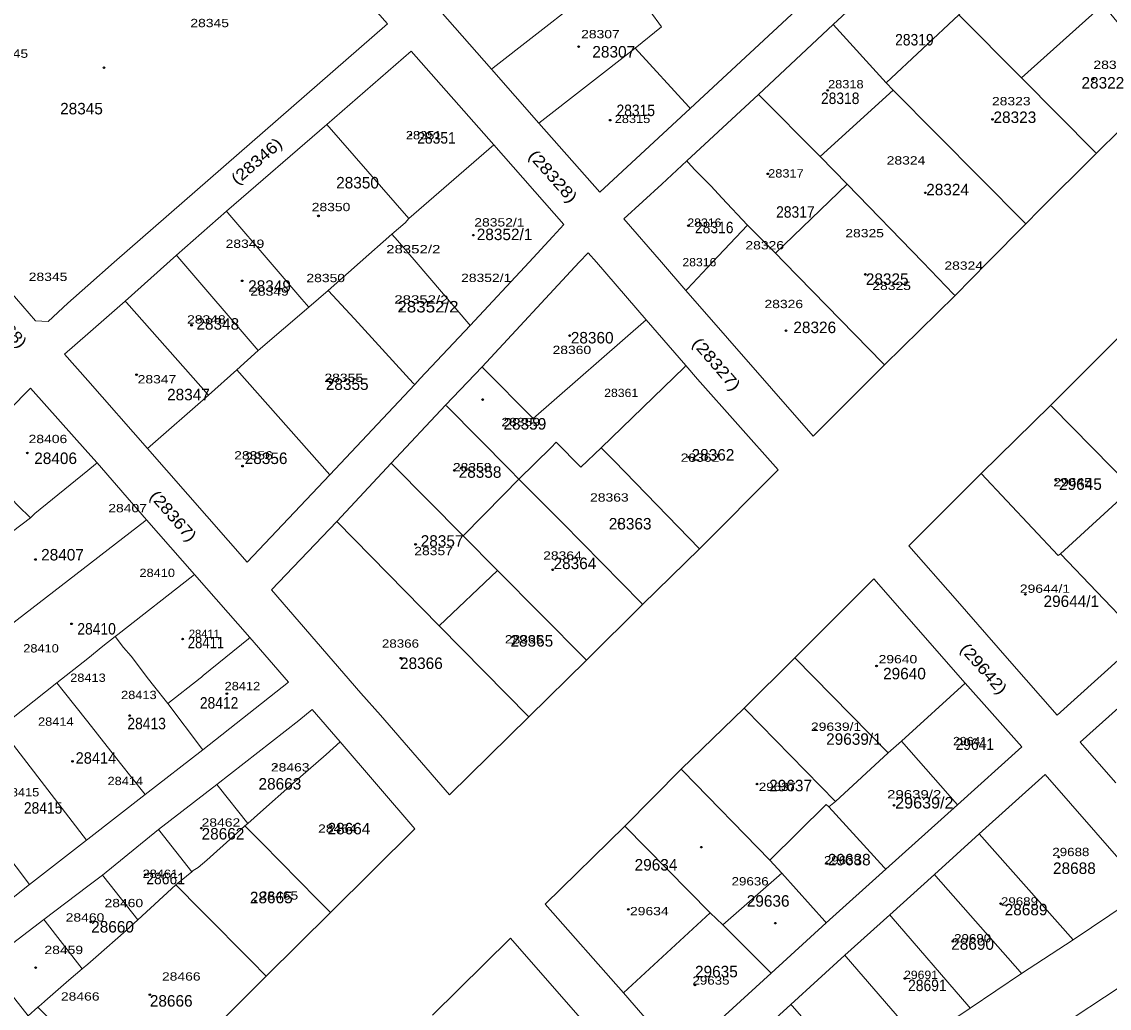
# Model space of a CAD drawing. Extents: x 650553 to 652508, y 239277 to 241647.
# Drawn here: x 651729.3 to 652069.7, y 240766.6 to 241075.2 of the extents above; entities that cross this region are included whole.
import ezdxf

# ---------------------------------------------------------------- set-up
doc = ezdxf.new("R2010")
doc.units = 0
doc.header["$PDMODE"] = 32
doc.header["$PDSIZE"] = 0.5
for name, color, linetype in [('19', 7, 'Continuous'), ('20', 7, 'Continuous'), ('6', 7, 'Continuous')]:
    doc.layers.add(name, color=color, linetype=linetype)
doc.layers.add('3', color=7, linetype='Continuous', lineweight=13)
doc.layers.add('5', color=7, linetype='Continuous', lineweight=13)

msp = doc.modelspace()

# ---------------------------------------------------------------- linework, layer by layer
at = {"layer": '3'}
for p, q in [((651924.77, 240982), (651909.19, 240999.99)), ((651750, 240963.02), (651768.69, 240941.77)), ((651825.74, 240933.5), (651852.36, 240961.71)), ((652021.51, 240894.81), (652038.48, 240875.31)), ((651835.45, 240865.24), (651841.63, 240858.29)), ((651731.81, 240805.34), (651749.66, 240819.26)), ((651825.99, 240796.59), (651805.82, 240776.71))]:
    msp.add_line(p, q, dxfattribs=at)
for points in [[(652017.226, 241141.527), (652026.85, 241129.84), (651999.05, 241104.25), (651938.56, 241048.11), (651910.25, 241021.92), (651891.181, 241043.471), (651876.36, 241060.41), (651857.991, 241081.221), (651845.55, 241095.34), (651829.37, 241113.9)], [(651737.63, 240981.45), (651733.68, 240981.72), (651717.72, 241000), (651672.26, 241052.06), (651672.58, 241053.6), (651750, 241112.87), (651779.79, 241135.68), (651785.77, 241140.28)], [(651785.77, 241140.28), (651790.81, 241134.55), (651843.78, 241074.53), (651758.28, 241000), (651750, 240992.68), (651743.815, 240987.217), (651737.63, 240981.45)], [(651983.33, 241074.4), (652010.17, 241099.35), (652014.44, 241103.34), (652034.04, 241121.44)], [(652067.78, 241080.53), (652087.98, 241056.04), (652065.72, 241034.07)], [(651959.92, 241052.49), (651959.88, 241052.46), (651983.33, 241074.4)], [(651877.11, 241036.75), (651851.25, 241066.02), (651824.88, 241043.11)], [(651937.23, 240991.2), (651929.59, 240999.98), (651917.75, 241013.6), (651929.68, 241024.44), (651937.53, 241031.7), (651959.92, 241052.49)], [(651750, 240977.6), (651761.72, 240987.86), (651777.78, 241002.17), (651793.43, 241015.96), (651824.88, 241043.11)], [(651888.11, 240999.99), (651895.59, 241008.03), (651898.96, 241011.76), (651877.11, 241036.75)], [(652065.72, 241034.07), (652047.38, 241015.92), (652044.07, 241012.53), (652043.58, 241011.99)], [(652043.58, 241011.99), (652031.74, 240999.98), (652021.48, 240989.55), (651999.33, 240967.9), (651976.99, 240945.59), (651937.23, 240991.2)], [(651909.19, 240999.99), (651906.59, 241002.99), (651903.81, 240999.99)], [(651903.81, 240999.99), (651873.4, 240967.25), (651862.01, 240955.34), (651844.95, 240937.15), (651827.99, 240918.9)], [(651852.36, 240961.71), (651854.09, 240963.61), (651869.71, 240980.19), (651888.11, 240999.99)], [(652029.57, 240933.88), (652051.36, 240955.22), (652072.28, 240976.15), (652095.19, 240998.75), (652096.4, 240999.97)], [(651940.85, 240963.44), (651937.22, 240967.66), (651924.77, 240982)], [(651750, 240977.6), (651742.76, 240971.25), (651750, 240963.02)], [(651941.49, 240910.36), (651966.07, 240935.03), (651940.85, 240963.44)], [(651712.06, 240940.35), (651732.06, 240960.6), (651750, 240940.5)], [(651768.69, 240941.77), (651799.93, 240906.14), (651825.74, 240933.5)], [(651812.82, 240868.68), (651800.77, 240882.58), (651783.43, 240902.3), (651768.4, 240919.43), (651752.95, 240937.2), (651750, 240940.5)], [(652021.51, 240894.81), (652006.93, 240911.31), (652029.57, 240933.88)], [(651827.99, 240918.9), (651807.54, 240897.54), (651835.45, 240865.24)], [(651888.09, 240857.77), (651906.06, 240875.49), (651923.67, 240892.98), (651941.49, 240910.36)], [(651971.34, 240876.28), (651996.04, 240900.92), (652024.65, 240868.28)], [(652038.48, 240875.31), (652053.43, 240858.34), (652079.85, 240882.2)], [(651918.05, 240823.64), (651935.73, 240841.37), (651955.41, 240860.55), (651971.34, 240876.28)], [(652071.8, 240837.17), (652060.65, 240849.83), (652086.59, 240873.17)], [(651785.973, 240847.456), (651786.03, 240847.5), (651812.82, 240868.68)], [(652024.65, 240868.28), (652042.35, 240848.37), (652022.25, 240830.22)], [(651828.96, 240849.94), (651820.2, 240860.04), (651816.02, 240856.68)], [(651736.3, 240794.4), (651750, 240804.78), (651754.61, 240808.27), (651772.19, 240822.5), (651790.39, 240836.59), (651816.02, 240856.68)], [(651841.63, 240858.29), (651863.19, 240833.39), (651888.09, 240857.77)], [(651825.99, 240796.59), (651852.4, 240822.8), (651828.96, 240849.94)], [(651749.66, 240819.26), (651750, 240819.52), (651767.96, 240833.48), (651785.973, 240847.456)], [(652029.04, 240821.24), (652049.7, 240839.74), (652081.4, 240803.43), (652058.39, 240788.05)], [(652022.25, 240830.22), (651999.75, 240810.11), (651981.15, 240793.34), (651963.94, 240777.64)], [(651917.67, 240771.45), (651893.13, 240799.24), (651918.05, 240823.64)], [(651950.46, 240750), (651970.1, 240767.82), (651986.91, 240783.26), (652001.01, 240795.81), (652014.98, 240808.48), (652029.04, 240821.24)], [(651731.81, 240805.34), (651713.76, 240791.05), (651698.26, 240811.09)], [(652130.48, 240811.26), (652125, 240807.76), (652110.91, 240798.75), (652092.01, 240785.99), (652073.09, 240773.31), (652053.84, 240760.57)], [(651666.816, 240692.253), (651642.596, 240721.898), (651682.54, 240752.71), (651700.34, 240766.81), (651718.3, 240780.69), (651736.3, 240794.4)], [(651857.87, 240764.46), (651882.29, 240788.58), (651910.691, 240756.161)], [(652058.39, 240788.05), (652042.27, 240777.48), (652026.22, 240766.64), (652010.4, 240756.05)], [(651963.94, 240777.64), (651935.1, 240751.32), (651917.67, 240771.45)], [(651805.82, 240776.71), (651779.01, 240750), (651765.5, 240736.54), (651749.871, 240721.656)]]:
    msp.add_lwpolyline(points, dxfattribs=at)
at = {"layer": '5'}
for p, q in [((651921.28, 241066.98), (651891.181, 241043.471)), ((651979.18, 241033.11), (652002.09, 241053.88)), ((651987.64, 241024.46), (652011.37, 240999.98)), ((651956.51, 241011.57), (651945.54, 240999.98)), ((651968.01, 240999.98), (651965.22, 241002.84)), ((651825.27, 240991.12), (651835.27, 240999.99)), ((651889.37, 240951.15), (651924.77, 240982)), ((651796.62, 240966.3), (651803.34, 240972.4)), ((651894.99, 240942.09), (651896.58, 240943.72)), ((651914.77, 240937.9), (651910.68, 240941.95)), ((651914.77, 240937.9), (651941.49, 240910.36)), ((651878.24, 240903.55), (651867.53, 240914.39)), ((652054.4, 240908.79), (652079.85, 240882.2)), ((651859.97, 240886.3), (651888.09, 240857.77)), ((651758.59, 240882.9), (651759.45, 240883.57)), ((652004.7, 240850.14), (652024.65, 240868.28)), ((651984, 240831.33), (652000.54, 240846.49)), ((652029.04, 240821.24), (652058.39, 240788.05)), ((651948.76, 240792.69), (651967.25, 240808.86)), ((651765.65, 240794.27), (651777.555, 240805.204)), ((651785.53, 240797.18), (651777.555, 240805.204)), ((651748.28, 240778.98), (651744.1, 240775.4)), ((651750, 240780.46), (651748.28, 240778.98)), ((651734.39, 240766.92), (651735.38, 240767.79))]:
    msp.add_line(p, q, dxfattribs=at)
for points in [[(651916.06, 241091.42), (651876.86, 241060.801), (651876.36, 241060.41)], [(652030.93, 241084.96), (652022.59, 241077.39), (651999.92, 241056.14)], [(652067.78, 241080.53), (652067.28, 241080.083), (652042.2, 241057.65), (652022.59, 241077.39)], [(651925.9, 241078.62), (651929.61, 241073.6), (651921.28, 241066.98)], [(651983.33, 241074.4), (651999.92, 241056.14), (652002.09, 241053.88)], [(651921.28, 241066.98), (651938.102, 241048.61), (651938.56, 241048.11)], [(652042.2, 241057.65), (652065.221, 241034.57), (652065.72, 241034.07)], [(652002.09, 241053.88), (652043.085, 241012.49), (652043.58, 241011.99)], [(651937.53, 241031.7), (651937.961, 241031.2), (651939.96, 241028.88), (651945.1, 241023.75), (651948.44, 241020.15), (651956.51, 241011.57), (651965.22, 241002.84), (651987.64, 241024.46), (651979.18, 241033.11), (651959.92, 241052.49)], [(651824.88, 241043.11), (651850.49, 241013.64), (651877.11, 241036.75)], [(651793.43, 241015.96), (651793.858, 241015.46), (651807.08, 241000)], [(651850.49, 241013.64), (651849.33, 241012.33), (651845.14, 241008.75), (651835.27, 240999.99)], [(651852.75, 240999.99), (651846.94, 241006.77), (651845.14, 241008.75)], [(651803.34, 240972.4), (651778.209, 241001.67), (651777.78, 241002.17)], [(651807.08, 241000), (651816.96, 240988.45), (651819.25, 240985.9), (651803.34, 240972.4)], [(651852.75, 240999.99), (651869.282, 240980.69), (651869.71, 240980.19)], [(651945.54, 240999.98), (651937.703, 240991.7), (651937.23, 240991.2)], [(651968.01, 240999.98), (651998.842, 240968.4), (651999.33, 240967.9)], [(652011.37, 240999.98), (652020.995, 240990.05), (652021.48, 240989.55)], [(651819.25, 240985.9), (651825.27, 240991.12), (651833.47, 240982.33)], [(651787.8, 240958.43), (651762.163, 240987.36), (651761.72, 240987.86)], [(651833.47, 240982.33), (651851.902, 240962.21), (651852.36, 240961.71)], [(651768.69, 240941.77), (651787.8, 240958.43), (651796.62, 240966.3), (651825.74, 240933.5)], [(651873.4, 240967.25), (651873.896, 240966.75), (651889.37, 240951.15)], [(651937.22, 240967.66), (651936.72, 240967.176), (651910.68, 240941.95)], [(651862.01, 240955.34), (651862.506, 240954.84), (651882.11, 240935.08), (651884.94, 240932.09), (651898.61, 240918.47)], [(652051.36, 240955.22), (652051.853, 240954.72), (652076.91, 240929.32)], [(652054.4, 240908.79), (652076.91, 240929.32), (652098.09, 240948.54)], [(651867.53, 240914.39), (651880.14, 240927.2), (651884.94, 240932.09), (651894.99, 240942.09)], [(651910.68, 240941.95), (651904.32, 240935.86), (651896.58, 240943.72)], [(651750, 240934.8), (651733.48, 240921.37), (651732.05, 240920.07), (651728.26, 240923.78), (651722.22, 240930.07), (651712.06, 240940.35)], [(651752.95, 240937.2), (651752.45, 240936.793), (651750, 240934.8)], [(651867.53, 240914.39), (651845.446, 240936.65), (651844.95, 240937.15)], [(652029.57, 240933.88), (652053.74, 240908.25), (652054.4, 240908.79)], [(651713.094, 240876.806), (651767.9, 240919.045), (651768.4, 240919.43)], [(651732.05, 240920.07), (651723.48, 240913.44), (651715.51, 240907.39)], [(651827.99, 240918.9), (651859.97, 240886.3), (651878.24, 240903.55)], [(651898.61, 240918.47), (651923.178, 240893.48), (651923.67, 240892.98)], [(651878.24, 240903.55), (651905.564, 240875.99), (651906.06, 240875.49)], [(651759.45, 240883.57), (651782.93, 240901.909), (651783.43, 240902.3)], [(651785.57, 240870.227), (651785.16, 240869.906), (651775.02, 240861.97), (651770.62, 240867.62), (651769.03, 240869.62), (651763.58, 240876.74), (651761.23, 240879.53), (651758.59, 240882.9), (651754.75, 240879.85), (651750, 240876.09)], [(651800.77, 240882.58), (651800.27, 240882.174), (651786.16, 240870.706), (651785.57, 240870.227)], [(651708.23, 240872.56), (651708.622, 240872.06), (651722.51, 240854.34), (651740.3, 240868.43), (651750, 240876.09)], [(651971.34, 240876.28), (652000.54, 240846.49), (652004.7, 240850.14), (652022.25, 240830.22)], [(651740.3, 240868.43), (651742.32, 240865.93), (651750, 240856.19)], [(651785.973, 240847.456), (651785.593, 240847.96), (651775.02, 240861.97)], [(651955.41, 240860.55), (651955.899, 240860.05), (651984, 240831.33), (651981.92, 240829.6)], [(651767.96, 240833.48), (651767.563, 240833.98), (651760.26, 240843.17), (651750, 240856.19)], [(651722.51, 240854.34), (651723.48, 240853.25), (651724.39, 240852.09), (651749.66, 240819.26)], [(651828.96, 240849.94), (651824.63, 240846.06), (651814.23, 240836.89), (651804.06, 240827.93)], [(651704.72, 240840.47), (651707.99, 240836.04), (651712.92, 240829.92), (651716.78, 240824.93), (651719.91, 240820.96), (651723.46, 240816.36), (651731.81, 240805.34)], [(651935.73, 240841.37), (651936.219, 240840.87), (651963.46, 240813), (651967.25, 240808.86)], [(651790.39, 240836.59), (651790.786, 240836.09), (651800.06, 240824.38)], [(651963.46, 240813), (651981.12, 240830.41), (651981.92, 240829.6)], [(651981.92, 240829.6), (651999.293, 240810.61), (651999.75, 240810.11)], [(651795.51, 240820.38), (651799.16, 240823.7), (651800.06, 240824.38), (651804.06, 240827.93)], [(651772.19, 240822.5), (651772.583, 240822), (651782.529, 240809.355), (651777.555, 240805.204)], [(651825.99, 240796.59), (651821.82, 240800.72), (651804.59, 240818.24), (651799.16, 240823.7)], [(651918.05, 240823.64), (651944.81, 240796.43), (651917.67, 240771.45)], [(651782.529, 240809.355), (651783.029, 240809.686), (651784.56, 240810.7), (651787.32, 240812.95), (651795.51, 240820.38)], [(651754.61, 240808.27), (651755.004, 240807.77), (651765.65, 240794.27)], [(651967.25, 240808.86), (651980.702, 240793.84), (651981.15, 240793.34)], [(652014.98, 240808.48), (652015.42, 240807.98), (652041.83, 240777.98), (652042.27, 240777.48)], [(651736.3, 240794.4), (651736.688, 240793.9), (651748.28, 240778.98)], [(651805.82, 240776.71), (651805.33, 240777.21), (651801.69, 240780.92), (651785.53, 240797.18)], [(651944.81, 240796.43), (651948.76, 240792.69), (651963.94, 240777.64)], [(652001.01, 240795.81), (652001.442, 240795.31), (652025.788, 240767.14), (652026.22, 240766.64)], [(651765.65, 240794.27), (651761.99, 240790.97), (651752.52, 240782.62), (651750, 240780.46)], [(651986.91, 240783.26), (651987.342, 240782.76), (652009.968, 240756.55), (652010.4, 240756.05)], [(651718.3, 240780.69), (651718.697, 240780.19), (651731.34, 240764.27), (651734.39, 240766.92), (651736.58, 240764.83), (651750, 240751.45)], [(651744.1, 240775.4), (651736.61, 240768.88), (651735.38, 240767.79)], [(651970.1, 240767.82), (651970.539, 240767.32), (651985.73, 240750)]]:
    msp.add_lwpolyline(points, dxfattribs=at)
at = {"layer": '6'}
for p in [(651903.616, 241067.445), (651755.087, 241060.865), (652064.745, 241057.3), (651981.608, 241053.755), (651913.519, 241044.45), (652033.16, 241044.69), (651851.06, 241039.83), (651962.841, 241027.665), (652012.124, 241021.715), (651822.207, 241014.505), (651938.008, 241011.45), (651870.691, 241008.47), (651993.387, 240996.18), (651798.349, 240994.18), (651848.079, 240985.23), (651782.488, 240980.3), (651968.567, 240978.58), (651900.817, 240977.07), (651765.281, 240964.815), (651825.986, 240962.31), (651873.582, 240957.045), (651731.111, 240940.335), (651938.093, 240939.01), (651798.441, 240936.22), (651864.765, 240934.865), (652053.06, 240931.735), (651916.233, 240918.35), (651852.596, 240911.725), (651733.64, 240907.003), (651895.522, 240903.79), (652043.449, 240896.11), (651744.933, 240886.885), (651779.706, 240882.135), (651883.231, 240880.66), (651848.003, 240876.145), (651996.879, 240873.705), (651793.551, 240865.018), (651763.148, 240858.19), (651977.69, 240853.805), (652023.526, 240849.25), (651745.232, 240843.845), (651808.912, 240842.21), (651959.447, 240836.775), (652002.347, 240830.125), (651785.58, 240822.972), (651825.796, 240823.265), (651942.036, 240817.03), (651981.313, 240811.875), (652053.899, 240813.895), (651768.059, 240808.385), (651802.432, 240800.205), (651919.17, 240797.545), (652035.699, 240799.36), (651750.918, 240793.625), (651965.226, 240793.25), (652020.768, 240787.56), (651733.69, 240779.335), (651940.06, 240773.875), (652005.715, 240775.93), (651769.429, 240770.872)]:
    msp.add_point(p, dxfattribs=at)

# ---------------------------------------------------------------- texts
at = {"layer": '19'}
for s, width, p in [('28319', 0.9, (652002.695, 241067.806)), ('28318', 0.9, (651979.476, 241049.486)), ('28315', 0.9, (651915.49, 241045.716)), ('28351', 0.9, (651853.125, 241037.093)), ('28317', 0.9, (651965.438, 241013.923)), ('28316', 0.9, (651940.059, 241009.074)), ('28352/2', 1.1, (651846.915, 240984.288)), ('28410', 0.9, (651746.751, 240883.528)), ('28411', 0.85, (651781.309, 240879.217)), ('28412', 0.9, (651785.088, 240860.358)), ('28413', 0.9, (651762.41, 240853.892)), ('29641', 0.9, (652021.595, 240847.427)), ('28414', 0.95, (651746.211, 240843.116)), ('29639/2', 1.05, (652002.695, 240829.107)), ('28415', 0.9, (651730.012, 240827.49)), ('28661', 0.9, (651768.351, 240805.399)), ('28691', 0.9, (652006.745, 240771.994))]:
    msp.add_text(s, height=3.6, dxfattribs=dict(at, width=width)).set_placement(p)
for s, p in [('28307', (651907.931, 241064.037)), ('28322', (652061.011, 241054.336)), ('28345', (651741.351, 241046.253)), ('28323', (652033.473, 241043.559)), ('28350', (651827.746, 241023.084)), ('28324', (652012.413, 241020.929)), ('28352/1', (651871.754, 241006.919)), ('28325', (651993.515, 240992.91)), ('28349', (651800.209, 240990.754)), ('28348', (651784.009, 240978.9)), ('28360', (651901.182, 240974.59)), ('28326', (651970.838, 240977.823)), ('28355', (651824.507, 240960.041)), ('28347', (651774.83, 240956.808)), ('28359', (651880.124, 240947.648)), ('28362', (651938.98, 240937.949)), ('28406', (651733.252, 240936.872)), ('28356', (651799.13, 240936.872)), ('28358', (651866.084, 240932.561)), ('29645', (652053.993, 240928.789)), ('28363', (651913.062, 240916.396)), ('28357', (651854.206, 240911.008)), ('28407', (651735.412, 240906.698)), ('28364', (651895.782, 240904.004)), ('29644/1', (652049.132, 240892.149)), ('28365', (651882.284, 240879.756)), ('28366', (651847.726, 240872.752)), ('29640', (651998.915, 240869.519)), ('29639/1', (651981.096, 240849.043)), ('28663', (651803.449, 240835.035)), ('29637', (651963.278, 240834.495)), ('28662', (651785.63, 240819.409)), ('28664', (651825.047, 240821.025)), ('29638', (651981.636, 240811.326)), ('29634', (651921.16, 240809.709)), ('28688', (652052.102, 240808.634)), ('28665', (651800.749, 240799.472)), ('29636', (651956.258, 240798.394)), ('28689', (652036.983, 240795.702)), ('28660', (651751.072, 240790.312)), ('28690', (652020.244, 240784.926)), ('29635', (651940.059, 240776.302)), ('28666', (651769.431, 240767.143))]:
    msp.add_text(s, height=3.6, dxfattribs=at).set_placement(p)
for s, rotation, width, p in [('(28346)', 40.803, 1.15, (651796.796, 241024.054)), ('(28328)', 311.43, 1.2, (651887.688, 241033.163)), ('(28368)', 311.011, 1.15, (651716.05, 240987.226)), ('(28327)', 310.702, 1.2, (651938.931, 240974.507)), ('(28367)', 311.005, 1.15, (651769.164, 240926.668)), ('(29642)', 311.236, 1.15, (652022.769, 240878.85))]:
    msp.add_text(s, height=3.6, rotation=rotation, dxfattribs=dict(at, width=width)).set_placement(p)
at = {"layer": '20'}
for s, width, p in [('28345', 1.25, (651782.118, 241073.534)), ('28307', 1.25, (651904.418, 241070.065)), ('28345', 1.25, (651719.263, 241063.952)), ('28322', 1.25, (652064.758, 241060.478)), ('28318', 1.15, (651981.705, 241054.394)), ('28323', 1.25, (652032.997, 241049.086)), ('28315', 1.15, (651914.931, 241043.538)), ('28351', 1.15, (651849.566, 241038.454)), ('28324', 1.25, (652000.05, 241030.562)), ('28317', 1.15, (651962.956, 241026.504)), ('28350', 1.25, (651820.101, 241015.974)), ('28352/1', 1.25, (651870.983, 241011.179)), ('28316', 1.1, (651937.687, 241011.099)), ('28325', 1.25, (651987.101, 241007.799)), ('28349', 1.25, (651793.159, 241004.497)), ('28352/2', 1.35, (651843.398, 241002.779)), ('28326', 1.25, (651955.835, 241004.016)), ('28316', 1.1, (651936.101, 240998.727)), ('28324', 1.25, (652018.11, 240997.656)), ('28345', 1.25, (651731.542, 240994.136)), ('28350', 1.25, (651818.443, 240993.766)), ('28352/1', 1.25, (651866.849, 240993.818)), ('28349', 1.25, (651800.84, 240989.545)), ('28325', 1.25, (651995.56, 240991.319)), ('28352/2', 1.35, (651845.946, 240987.058)), ('28326', 1.25, (651961.801, 240985.638)), ('28348', 1.25, (651781.094, 240980.819)), ('28360', 1.25, (651895.474, 240971.28)), ('28347', 1.25, (651765.628, 240962.097)), ('28355', 1.25, (651824.087, 240962.556)), ('28361', 1.1, (651911.636, 240957.842)), ('28359', 1.25, (651879.485, 240948.714)), ('28406', 1.25, (651731.501, 240943.412)), ('28356', 1.25, (651795.843, 240938.293)), ('28362', 1.25, (651935.572, 240937.565)), ('28358', 1.25, (651864.285, 240934.577)), ('29645', 1.25, (652052.196, 240929.901)), ('28363', 1.25, (651907.216, 240925.115)), ('28407', 1.25, (651756.44, 240921.783)), ('28357', 1.25, (651852.206, 240908.361)), ('28364', 1.25, (651892.532, 240906.95)), ('28410', 1.15, (651766.187, 240901.53)), ('29644/1', 1.25, (652041.733, 240896.589)), ('28365', 1.25, (651880.544, 240880.745)), ('28410', 1.15, (651729.826, 240877.921)), ('28366', 1.2, (651842.069, 240879.426)), ('29640', 1.25, (651997.522, 240874.522)), ('28413', 1.15, (651744.513, 240868.732)), ('28413', 1.15, (651760.441, 240863.342)), ('28412', 1.15, (651792.847, 240866.123)), ('28414', 1.15, (651734.452, 240855)), ('29639/1', 1.25, (651976.352, 240853.405)), ('29641', 1.1, (652020.831, 240848.914)), ('28463', 1.25, (651807.329, 240840.697)), ('28414', 1.15, (651756.2, 240836.433)), ('28415', 1.15, (651723.713, 240832.903)), ('29637', 1.2, (651960.019, 240834.611)), ('29639/2', 1.35, (652000.179, 240832.264)), ('28462', 1.25, (651785.638, 240823.437)), ('28464', 1.25, (651822.099, 240821.539)), ('29688', 1.2, (652051.888, 240814.219)), ('29638', 1.2, (651980.406, 240811.635)), ('28461', 1.15, (651767.164, 240807.4)), ('29636', 1.2, (651951.509, 240805.047)), ('28465', 1.25, (651803.798, 240800.602)), ('29689', 1.2, (652035.807, 240798.747)), ('28460', 1.25, (651755.255, 240798.24)), ('29634', 1.25, (651919.716, 240795.713)), ('28460', 1.25, (651743.105, 240793.74)), ('29690', 1.2, (652021.142, 240787.227)), ('28459', 1.25, (651736.459, 240783.578)), ('28466', 1.25, (651773.228, 240775.276)), ('29691', 1.1, (652005.482, 240775.784)), ('29635', 1.2, (651939.258, 240774.014)), ('28466', 1.25, (651741.604, 240769.02))]:
    msp.add_text(s, height=2.6, dxfattribs=dict(at, width=width)).set_placement(p)
msp.add_text('28411', height=2.6, dxfattribs=at).set_placement((651781.657, 240882.467))

doc.saveas('drawing.dxf')
